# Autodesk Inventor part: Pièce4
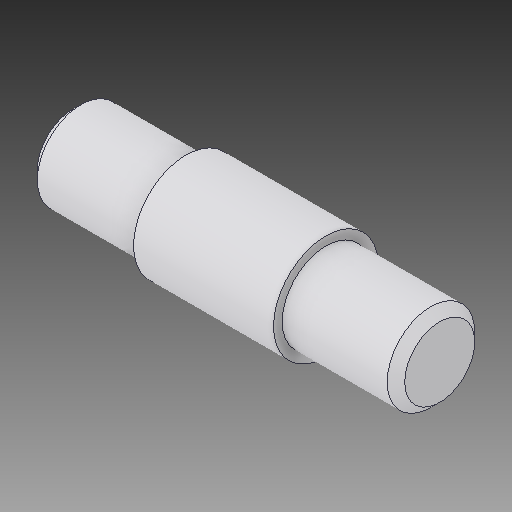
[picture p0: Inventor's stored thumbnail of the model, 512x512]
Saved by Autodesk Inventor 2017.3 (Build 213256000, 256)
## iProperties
Created: 2007-11
Part Number: Pièce4
Material: solidworks materials|Alliage 7079|22
Document SubType Name: Modeling
Designer: ficho
Density: 2.7 g/cm^3
Appearance: 227,227,233
Author: ficho
Sending System: SolidWorks 2009
Last Author: christophe
Last Saved: 2011-01-17
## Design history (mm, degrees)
feature "Chanfrein1"
node "Solide1"
